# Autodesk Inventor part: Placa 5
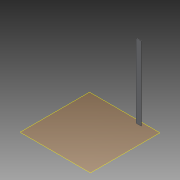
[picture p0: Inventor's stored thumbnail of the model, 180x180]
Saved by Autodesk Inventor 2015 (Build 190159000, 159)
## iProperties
Created: 2015-04
Part Number: Placa 5
Material: Generic
Document SubType Name: Modeling
Designer: suporte
Density: 1 g/cm^3
Appearance: Default
Author: suporte
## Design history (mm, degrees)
workplane "Work Plane1"
sketch "Sketch1"
  geometry: L1 (572.263, 900)-(430.862, 900); L2 (430.862, 900)-(430.862, 887.5); L3 (430.862, 887.5)-(572.263, 887.5); L4 (572.263, 887.5)-(572.263, 900); L5 (430.862, 900)-(430.862, 887.5) reference; 1 further point
  constraints: 8 end point, 2 parallel, 1 horizontal, 1 perpendicular
extrude "Extrusion1" new body sketch "Sketch1" distance "d0" = 2100; taper "d1" = 0 deg
body "Solid1"
node "Reference1"
node "Reference2"
